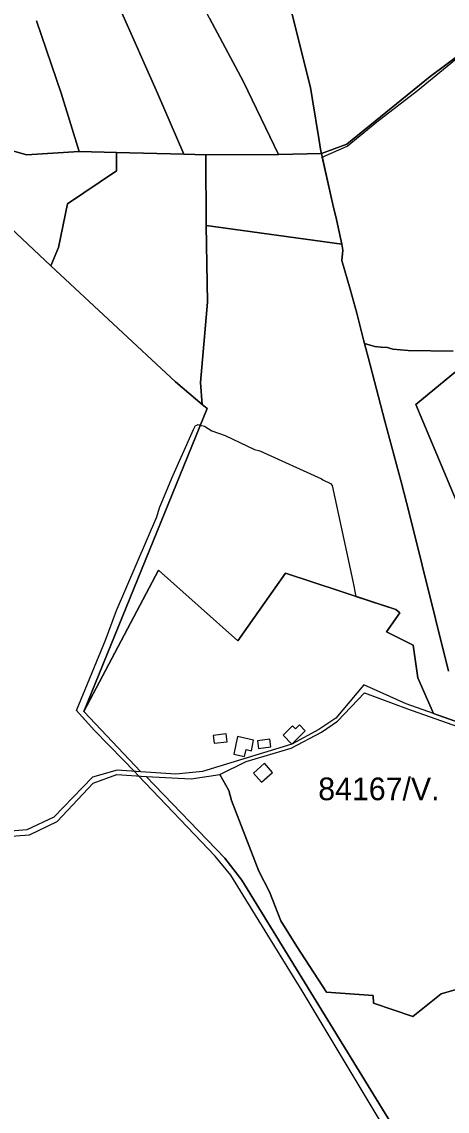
# Model space of a CAD drawing. Extents: x -477304 to -465429, y -1159113 to -1149210.
# Drawn here: x -470879 to -470597, y -1157709 to -1156987 of the extents above; entities that cross this region are included whole.
import ezdxf

# ---------------------------------------------------------------- set-up
doc = ezdxf.new("R2010")
doc.units = 0
for name, color, linetype in [('BPEJ_s', 7, 'Continuous'), ('PUPFL_s', 7, 'Continuous'), ('trav_porost_s', 7, 'Continuous')]:
    doc.layers.add(name, color=color, linetype=linetype)

msp = doc.modelspace()

# ---------------------------------------------------------------- linework, layer by layer
at = {"layer": 'BPEJ_s'}
for points in [[(-470661.39, -1157164.46), (-470666.93, -1157145.28), (-470666.1, -1157138.52), (-470666.91, -1157134.63), (-470670.33, -1157118.12), (-470672.72, -1157108.27), (-470679.83, -1157077), (-470663.38, -1157069.71), (-470643.68, -1157053.62), (-470616.74, -1157032.72), (-470579.94, -1157002.46), (-470557.02, -1157031.21), (-470546.97, -1157046.69), (-470532.29, -1157065.89), (-470531.11, -1157067.36), (-470529.88, -1157068.91), (-470478.21, -1157059.66), (-470475.08, -1157059.13), (-470412.86, -1157048.7), (-470346.52, -1157036.94), (-470334.66, -1157034.83), (-470335.1, -1157033.81), (-470340.15, -1157022.07), (-470382.21, -1156936.55)], [(-470596.25, -1157417.29), (-470622.39, -1157312.54), (-470627.64, -1157291.89), (-470638.38, -1157251.82), (-470649.46, -1157209.43), (-470651.83, -1157200.37), (-470652.48, -1157197.92), (-470657, -1157180.17), (-470661.39, -1157164.46), (-470666.93, -1157145.28), (-470666.1, -1157138.52), (-470666.91, -1157134.63), (-470670.33, -1157118.12), (-470672.72, -1157108.27), (-470679.83, -1157077), (-470663.38, -1157069.71), (-470643.68, -1157053.62), (-470616.74, -1157032.72), (-470579.94, -1157002.46)], [(-470593.18, -1157205.37), (-470622.96, -1157204.95), (-470633.17, -1157204.1), (-470634.65, -1157203.64), (-470636.57, -1157203.03), (-470640.82, -1157202.71), (-470645.08, -1157202.4), (-470648.04, -1157201.51), (-470651.83, -1157200.37), (-470652.48, -1157197.92), (-470657, -1157180.17), (-470661.39, -1157164.46)], [(-470596.25, -1157417.29), (-470622.39, -1157312.54), (-470627.64, -1157291.89), (-470638.38, -1157251.82), (-470649.46, -1157209.43), (-470651.83, -1157200.37), (-470648.04, -1157201.51), (-470645.08, -1157202.4), (-470640.82, -1157202.71), (-470636.57, -1157203.03), (-470634.65, -1157203.64), (-470633.17, -1157204.1), (-470622.96, -1157204.95), (-470593.18, -1157205.37)], [(-470640.82, -1157716.22), (-470693.14, -1157629.02), (-470740.36, -1157552.46), (-470750.78, -1157539.7), (-470801.52, -1157486.61), (-470804.38, -1157483.62), (-470811.47, -1157476.2), (-470830.75, -1157456.33), (-470842.51, -1157443.41), (-470823.3, -1157396.78), (-470816.07, -1157377.22), (-470789.27, -1157315.11), (-470787.57, -1157309.16), (-470779.49, -1157289.59), (-470765.03, -1157257.27), (-470763.75, -1157254.71), (-470762.87, -1157254.39), (-470762.05, -1157254.08), (-470760.59, -1157254.44), (-470757.8, -1157255.14), (-470753, -1157258.14), (-470744.18, -1157261.31), (-470724.62, -1157270.45), (-470721.22, -1157271.3), (-470680.38, -1157290.02), (-470679.39, -1157290.52), (-470674.43, -1157293), (-470673.15, -1157294.27), (-470659.54, -1157357.65), (-470657.56, -1157367.82), (-470631.15, -1157376.5), (-470628.55, -1157378.73), (-470637.3, -1157391.35), (-470619.66, -1157400.15), (-470616.61, -1157421.73), (-470606.24, -1157445.32)], [(-470640.82, -1157716.22), (-470693.14, -1157629.02), (-470740.36, -1157552.46), (-470750.78, -1157539.7), (-470801.52, -1157486.61), (-470804.38, -1157483.62), (-470811.47, -1157476.2), (-470830.75, -1157456.33), (-470842.51, -1157443.41), (-470823.3, -1157396.78), (-470816.07, -1157377.22), (-470789.27, -1157315.11), (-470787.57, -1157309.16), (-470779.49, -1157289.59), (-470765.03, -1157257.27), (-470763.75, -1157254.71), (-470762.87, -1157254.39), (-470762.05, -1157254.08), (-470760.59, -1157254.44), (-470757.8, -1157255.14), (-470753, -1157258.14), (-470744.18, -1157261.31), (-470724.62, -1157270.45), (-470721.22, -1157271.3), (-470680.38, -1157290.02), (-470679.39, -1157290.52), (-470674.43, -1157293), (-470673.15, -1157294.27), (-470659.54, -1157357.65), (-470657.56, -1157367.82), (-470631.15, -1157376.5), (-470628.55, -1157378.73), (-470637.3, -1157391.35), (-470619.66, -1157400.15), (-470616.61, -1157421.73), (-470606.24, -1157445.32), (-470592.41, -1157450.19)], [(-470606.24, -1157445.32), (-470592.41, -1157450.19)]]:
    msp.add_lwpolyline(points, dxfattribs=at)
at = {"layer": 'PUPFL_s'}
for points in [[(-470682, -1157064.52), (-470680.67, -1157073.06), (-470680.4, -1157074.52), (-470708.84, -1157075.26), (-470731.97, -1157027.06), (-470754.51, -1156984.97), (-470803.02, -1156894.61), (-470831.18, -1156842.78)], [(-470837.95, -1156923.96), (-470788.91, -1157034.56), (-470771.43, -1157074.99), (-470816.01, -1157073.77), (-470840.63, -1157073.1), (-470852.74, -1157034.5), (-470868.9, -1156986.68)], [(-470754.51, -1156984.97), (-470731.97, -1157027.06), (-470708.84, -1157075.26), (-470756.87, -1157075.45), (-470771.43, -1157074.99), (-470788.91, -1157034.56), (-470837.95, -1156923.96)], [(-470509.57, -1156955.48), (-470575.61, -1156999.08), (-470608.45, -1157023.53), (-470663.56, -1157068.29), (-470680.4, -1157074.52), (-470680.67, -1157073.06), (-470682, -1157064.52), (-470686.31, -1157038.97), (-470687.64, -1157030.91), (-470700.64, -1156979.02)], [(-470868.9, -1156986.68), (-470852.74, -1157034.5), (-470840.63, -1157073.1), (-470875.56, -1157075.32), (-470908.78, -1157066.01), (-470920.24, -1157010.77), (-470931.25, -1156957.72)], [(-470700.64, -1156979.02), (-470687.64, -1157030.91), (-470686.31, -1157038.97), (-470682, -1157064.52)], [(-470596.25, -1157417.29), (-470622.39, -1157312.54), (-470627.64, -1157291.89), (-470638.38, -1157251.82), (-470649.46, -1157209.43), (-470652.48, -1157197.92), (-470657, -1157180.17), (-470661.39, -1157164.46), (-470666.93, -1157145.28), (-470666.1, -1157138.52), (-470666.91, -1157134.63), (-470670.33, -1157118.12), (-470672.72, -1157108.27), (-470680.4, -1157074.52), (-470663.56, -1157068.29), (-470608.45, -1157023.53), (-470575.61, -1156999.08)], [(-470958.6, -1157055.74), (-470859.49, -1157148.84), (-470777.05, -1157225.63), (-470759.21, -1157240.65), (-470756.06, -1157243.3), (-470837.71, -1157444.09), (-470799.88, -1157483.91), (-470815.67, -1157482.89), (-470832.01, -1157487.54), (-470857.42, -1157514.04), (-470875.29, -1157522.37), (-470888.71, -1157523.4)], [(-470587.46, -1157451.93), (-470606.24, -1157445.32), (-470616.61, -1157421.73), (-470619.66, -1157400.15), (-470637.3, -1157391.35), (-470628.55, -1157378.73), (-470631.15, -1157376.5), (-470704.25, -1157352.47), (-470735.74, -1157397.27), (-470788.18, -1157350.53), (-470837.71, -1157444.09), (-470756.06, -1157243.3), (-470759.21, -1157240.65), (-470760.39, -1157226.07), (-470755.88, -1157173.01), (-470756.73, -1157122.19), (-470666.91, -1157134.63), (-470666.1, -1157138.52), (-470666.93, -1157145.28), (-470661.39, -1157164.46), (-470657, -1157180.17), (-470652.48, -1157197.92), (-470649.46, -1157209.43), (-470638.38, -1157251.82), (-470627.64, -1157291.89), (-470622.39, -1157312.54), (-470596.25, -1157417.29)], [(-470555.29, -1157189), (-470617.79, -1157240.8), (-470585.54, -1157317.95)], [(-470921.41, -1157709.53), (-470953.47, -1157685.89), (-471012.1, -1157640.45), (-471033.37, -1157630.01), (-471073.61, -1157621.9), (-471104, -1157613.53), (-471134.85, -1157594.16), (-471169.15, -1157554.35), (-471187.9, -1157516.76), (-471170.18, -1157520.05), (-471120.87, -1157508.96), (-471109.39, -1157506.38), (-471014.13, -1157517.7), (-470969.16, -1157517.72), (-470944.32, -1157518.43), (-470888.77, -1157526.84), (-470873.56, -1157525.61), (-470855.26, -1157516.81), (-470831.39, -1157491.55), (-470815.69, -1157485.69), (-470796.29, -1157486.95), (-470744.24, -1157541.08), (-470733.12, -1157555.79), (-470617.41, -1157743.87)], [(-470617.41, -1157743.87), (-470733.12, -1157555.79), (-470744.24, -1157541.08), (-470796.29, -1157486.95), (-470766.49, -1157488.63), (-470747.6, -1157485.71), (-470741.7, -1157496.4), (-470739.92, -1157502.99), (-470721.9, -1157549.78), (-470714.65, -1157563.47), (-470707.23, -1157582.69), (-470696.61, -1157599.68), (-470677.11, -1157629.87), (-470646.13, -1157632.05), (-470645.81, -1157637.07), (-470619.81, -1157645.92), (-470601.07, -1157630.87), (-470577.46, -1157624.19)]]:
    msp.add_lwpolyline(points, dxfattribs=at)
for points in [[(-470859.49, -1157148.84), (-470958.6, -1157055.74), (-470908.78, -1157066.01), (-470875.56, -1157075.32), (-470840.63, -1157073.1), (-470816.01, -1157073.77), (-470815.91, -1157085.9), (-470848.5, -1157107.87), (-470854.31, -1157136.83)], [(-470815.91, -1157085.9), (-470816.01, -1157073.77), (-470771.43, -1157074.99), (-470756.87, -1157075.45), (-470756.73, -1157122.19), (-470755.88, -1157173.01), (-470760.39, -1157226.07), (-470759.21, -1157240.65), (-470777.05, -1157225.63), (-470859.49, -1157148.84), (-470854.31, -1157136.83), (-470848.5, -1157107.87)], [(-470672.72, -1157108.27), (-470670.33, -1157118.12), (-470666.91, -1157134.63), (-470756.73, -1157122.19), (-470756.87, -1157075.45), (-470708.84, -1157075.26), (-470680.4, -1157074.52)]]:
    msp.add_lwpolyline(points, close=True, dxfattribs=at)
at = {"layer": 'trav_porost_s'}
for points in [[(-470550.2, -1157376.95), (-470560.16, -1157349.75), (-470585.54, -1157317.95), (-470617.79, -1157240.8), (-470555.29, -1157189), (-470510.65, -1157276.42), (-470504.27, -1157289.34)], [(-470759.16, -1157483.71), (-470776.71, -1157485.4), (-470799.88, -1157483.91), (-470837.71, -1157444.09), (-470788.18, -1157350.53), (-470735.74, -1157397.27), (-470704.25, -1157352.47), (-470631.15, -1157376.5), (-470628.55, -1157378.73), (-470637.3, -1157391.35), (-470619.66, -1157400.15), (-470616.61, -1157421.73), (-470606.24, -1157445.32), (-470624.3, -1157438.97), (-470652.26, -1157426.44), (-470670.75, -1157448.51), (-470682.05, -1157455.99), (-470700, -1157465.56), (-470691.08, -1157456.76), (-470694.98, -1157452.81), (-470697.61, -1157455.41), (-470699.48, -1157453.51), (-470705.77, -1157459.71), (-470700, -1157465.56)], [(-470707.23, -1157582.69), (-470714.65, -1157563.47), (-470721.9, -1157549.78), (-470739.92, -1157502.99), (-470741.7, -1157496.4), (-470747.6, -1157485.71), (-470730.25, -1157477.23), (-470700.37, -1157468.28), (-470680.38, -1157457.72), (-470669.73, -1157450.45), (-470651.79, -1157431.55), (-470623.43, -1157442.33), (-470586.63, -1157455.18), (-470572.21, -1157543.49), (-470571.26, -1157548.95), (-470569.65, -1157589.72), (-470571.64, -1157608.47), (-470577.46, -1157624.19), (-470601.07, -1157630.87), (-470619.81, -1157645.92), (-470645.81, -1157637.07), (-470646.13, -1157632.05), (-470677.11, -1157629.87), (-470696.61, -1157599.68)], [(-470743.52, -1157458.7), (-470752.08, -1157459.84), (-470751.32, -1157465.07), (-470742.82, -1157464.02)], [(-470730.29, -1157469.22), (-470726.76, -1157469.99), (-470725.22, -1157462.93), (-470735.87, -1157460.61), (-470738.41, -1157472.27), (-470731.31, -1157473.84)], [(-470722.72, -1157463.39), (-470722.02, -1157468.59), (-470713.83, -1157467.48), (-470714.53, -1157462.29)], [(-470719.96, -1157490.87), (-470712.85, -1157484.35), (-470718.07, -1157478.24), (-470725.24, -1157484.9)]]:
    msp.add_lwpolyline(points, close=True, dxfattribs=at)

# ---------------------------------------------------------------- texts
at = {"layer": 'BPEJ_s'}
msp.add_text('84167/V.', height=15, dxfattribs=at).set_placement((-470682.48, -1157502.75))

doc.saveas('drawing.dxf')
